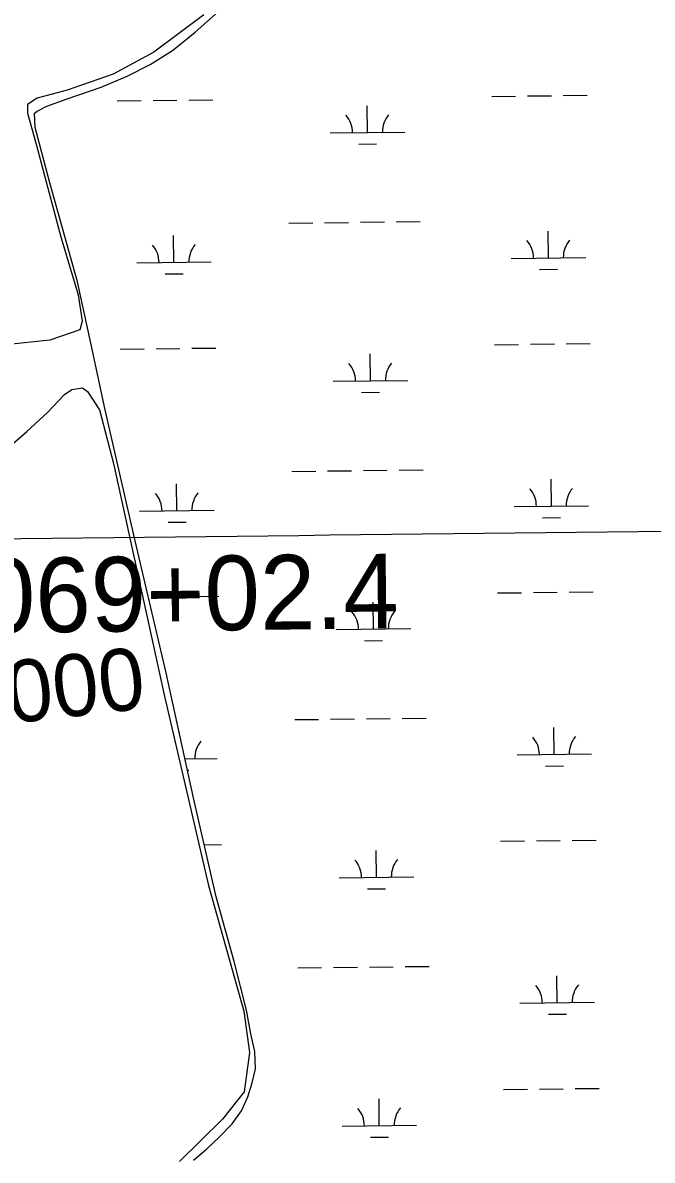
# Model space of a CAD drawing. Extents: x 3694830 to 3732949, y 415201 to 440970.
# Drawn here: x 3718917 to 3719761, y 426079 to 427603 of the extents above; entities that cross this region are included whole.
import ezdxf

# ---------------------------------------------------------------- set-up
doc = ezdxf.new("R2010")
doc.units = 0
for name, color, linetype in [('V-GRID-MAJR', 7, 'Continuous'), ('V-RIVR-EDGE', 7, 'Continuous'), ('V-RIVR-RANG-IDEN', 7, 'Continuous'), ('V-SITE-VEGE', 7, 'Continuous'), ('V-SURV-IDEN', 7, 'Continuous'), ('V-WETL-SWMP', 7, 'Continuous')]:
    doc.layers.add(name, color=color, linetype=linetype)

msp = doc.modelspace()

# ---------------------------------------------------------------- linework, layer by layer
at = {"layer": 'V-GRID-MAJR'}
msp.add_spline([(3698983.973, 426676.689), (3704276.781, 426737.893), (3709569.5810000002, 426799.866), (3714862.3710000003, 426862.61), (3720155.153, 426926.124), (3725447.9250000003, 426990.407), (3730740.688, 427055.46), (3730740.6890000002, 427055.46)], degree=3, dxfattribs=at)
at = {"layer": 'V-RIVR-EDGE'}
msp.add_spline([(3716285.150342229, 433216.70755455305), (3716310.376054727, 433178.2116670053), (3716330.200490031, 433149.67663238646), (3716351.384748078, 433122.4947121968), (3716380.6619774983, 433076.75426305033), (3716399.1355344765, 433050.48336356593), (3716447.785043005, 432976.2089978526), (3716475.253647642, 432930.4730209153), (3716501.833592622, 432891.0694668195), (3716527.508107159, 432851.21599263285), (3716586.0368507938, 432749.33550184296), (3716608.0997060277, 432711.75175305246), (3716608.0896435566, 432707.6823472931), (3716608.0717547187, 432700.4478481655), (3716613.02199377, 432690.94026948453), (3716627.4250269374, 432664.22727627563), (3716633.271752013, 432651.55236812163), (3716643.1890009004, 432639.3195536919), (3716675.1691050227, 432589.50299047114), (3716706.241542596, 432538.3321947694), (3716726.9412209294, 432498.0388629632), (3716741.3252472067, 432463.63921443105), (3716748.5083159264, 432442.8221406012), (3716788.5914538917, 432378.5164541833), (3716817.4332979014, 432339.5594660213), (3716842.1979097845, 432297.4474469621), (3716889.457408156, 432209.6117495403), (3716920.495186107, 432144.4241117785), (3716938.0431876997, 432109.5644806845), (3716956.496619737, 432075.15476968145), (3716988.92217174, 432022.6241512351), (3717009.1808744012, 431986.85349943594), (3717026.296844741, 431960.1337979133), (3717062.315049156, 431897.646798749), (3717093.371833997, 431840.1458163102), (3717112.2628875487, 431799.8569567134), (3717149.120557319, 431711.14266210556), (3717176.537731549, 431644.6075001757), (3717201.24867692, 431580.7919837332), (3717210.6835821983, 431556.3520700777), (3717248.473515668, 431478.93944425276), (3717267.8088990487, 431435.48437323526), (3717289.4072995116, 431392.9280243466), (3717306.4751936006, 431346.7656064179), (3717328.065767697, 431301.04416416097), (3717339.309297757, 431276.599778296), (3717352.341327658, 431244.01210870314), (3717362.697316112, 431226.35230187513), (3717376.210571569, 431205.5195753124), (3717389.256018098, 431178.3577800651), (3717401.373673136, 431141.70294081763), (3717407.1812663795, 431113.2025658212), (3717409.866252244, 431101.89195262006), (3717419.7488415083, 431075.6422961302), (3717452.4923834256, 430968.8518161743), (3717469.0935866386, 430916.8124857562), (3717483.4351269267, 430865.2309017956), (3717505.4543781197, 430810.0130613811), (3717526.565962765, 430753.4409884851), (3717540.488888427, 430715.4252084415), (3717579.0724471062, 430593.2468831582), (3717599.254004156, 430526.27745387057), (3717616.308481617, 430474.68916159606), (3717628.8760567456, 430437.12889190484), (3717638.7441113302, 430405.00120487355), (3717647.6866105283, 430364.284786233), (3717653.484141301, 430331.7150054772), (3717658.415373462, 430314.52077147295), (3717667.8502787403, 430290.08085781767), (3717679.533666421, 430260.6616357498), (3717690.3395749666, 430242.0963984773), (3717695.714018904, 430221.2837968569), (3717698.374407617, 430200.02574735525), (3717697.8529321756, 430171.9931812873), (3717701.423223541, 430152.9936766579), (3717705.9145980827, 430140.7742788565), (3717716.262760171, 430119.94937866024), (3717727.970745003, 430100.4775928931), (3717735.598143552, 430076.49430764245), (3717737.8164385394, 430059.3067819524), (3717749.0476700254, 430029.8886779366), (3717760.7590090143, 430011.77336075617), (3717771.5570911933, 429990.0430301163), (3717776.477142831, 429968.32723415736), (3717783.193520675, 429941.63324783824), (3717791.7252316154, 429917.6477264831), (3717803.4343344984, 429898.62809691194), (3717812.4226738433, 429876.4500822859), (3717819.158058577, 429857.44275129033), (3717834.8829007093, 429816.70956186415), (3717846.5238024, 429770.10840436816), (3717854.1232496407, 429734.8212142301), (3717863.5480924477, 429706.31189481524), (3717878.825250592, 429667.3884482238), (3717891.374936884, 429622.593679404), (3717903.4937099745, 429586.3909963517), (3717917.8240697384, 429530.28785043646), (3717931.7078635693, 429476.44660355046), (3717959.4631526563, 429363.79039162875), (3717976.505331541, 429307.2283812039), (3717987.2463930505, 429262.43808459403), (3718014.107432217, 429153.85351453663), (3718027.5144727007, 429090.0659494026), (3718040.473829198, 429028.0881271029), (3718052.5199288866, 428962.49529134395), (3718057.840706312, 428919.97919233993), (3718056.8950259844, 428903.2516492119), (3718056.857012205, 428887.87833856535), (3718057.7132483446, 428868.43338605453), (3718061.286893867, 428850.7903500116), (3718065.765969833, 428833.5972340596), (3718082.361582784, 428779.2971226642), (3718091.327561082, 428748.075984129), (3718100.2790047, 428710.97681505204), (3718111.4498613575, 428657.14227648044), (3718116.3609685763, 428631.80923095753), (3718128.3075616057, 428525.97449379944), (3718136.7677171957, 428473.0509759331), (3718141.6598175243, 428440.0312750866), (3718152.315907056, 428360.8771076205), (3718163.899788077, 428291.2159841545), (3718171.048197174, 428256.3820682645), (3718178.233501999, 428236.4693068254), (3718193.9158581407, 428178.55418197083), (3718199.7413402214, 428157.2883061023), (3718197.914826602, 428150.05827918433), (3718196.516990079, 428133.3318541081), (3718197.391115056, 428121.12140072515), (3718204.1164373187, 428098.04466397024), (3718215.364439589, 428075.4089028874), (3718227.961084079, 428049.60469427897), (3718240.07538496, 428011.5933864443), (3718242.706704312, 427978.57927585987), (3718251.1064850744, 427901.2393234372), (3718254.151946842, 427852.85078415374), (3718257.693168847, 427822.09521844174), (3718271.4975809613, 427736.1508816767), (3718281.7384100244, 427671.91898671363), (3718287.906479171, 427606.3406856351), (3718295.910006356, 427551.6096610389), (3718303.86545729, 427477.4359200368), (3718310.120734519, 427447.1258022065), (3718323.1359936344, 427407.755789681), (3718345.149654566, 427350.27716828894), (3718351.4094040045, 427321.7756752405), (3718363.483455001, 427267.48674436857), (3718378.280505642, 427217.2605109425), (3718397.9875454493, 427141.24907579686), (3718402.8729374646, 427105.51643777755), (3718405.9172811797, 427056.67574229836), (3718404.85644146, 426993.37611103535), (3718419.5841728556, 426915.1161934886), (3718427.128835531, 426857.673349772), (3718428.7697524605, 426789.8454482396), (3718439.5309389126, 426753.19396314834), (3718453.8926041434, 426709.7511907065), (3718458.333666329, 426677.1847641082), (3718461.822339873, 426625.1778572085), (3718465.3367286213, 426583.5705428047), (3718482.7136682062, 426479.5310138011), (3718492.5235840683, 426423.89120460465), (3718501.0016284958, 426378.20218586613), (3718502.740934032, 426350.1640295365), (3718512.9079716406, 426256.0898256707), (3718518.2276310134, 426213.12157047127), (3718524.0307520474, 426182.8125706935), (3718533.4421782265, 426148.87737693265), (3718540.932056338, 426069.2788796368), (3718548.926639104, 426010.93060547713), (3718557.8054093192, 425944.44128369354), (3718573.419564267, 425858.9446309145), (3718584.546816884, 425787.47600071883), (3718587.6079313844, 425745.4176481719), (3718587.5598551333, 425725.9749317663), (3718607.5144475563, 425567.2177947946), (3718614.553287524, 425488.07257174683), (3718638.2224000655, 425368.6440793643), (3718641.2633896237, 425318.44691529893), (3718641.093445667, 425249.71917358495), (3718640.1008071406, 425214.0010702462), (3718649.842521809, 425130.7797331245), (3718658.7335906, 425069.2641294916), (3718661.819302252, 425037.15321324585), (3718660.4114032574, 425016.35738241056), (3718674.9568921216, 424864.3960049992), (3718675.7337465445, 424812.8479626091), (3718692.623870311, 424694.7927095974), (3718696.053287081, 424618.8215243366), (3718696.3992283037, 424575.8655677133), (3718706.120818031, 424484.50541907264), (3718711.8680364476, 424431.58860952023), (3718715.414848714, 424403.0938247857), (3718735.932284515, 424289.09903311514), (3718746.6017906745, 424215.3707399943), (3718759.902616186, 424108.62833628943), (3718772.361740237, 424027.20891563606), (3718777.7160592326, 423998.2575024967), (3718795.9078670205, 423858.0432417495), (3718805.722255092, 423804.2120573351), (3718812.4363968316, 423776.6137586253), (3718828.995114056, 423707.3924927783), (3718835.666769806, 423662.61225864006), (3718835.0893917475, 423611.97188279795), (3718835.0021836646, 423576.70369954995), (3718839.347093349, 423505.2518401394), (3718842.400381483, 423460.0283942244), (3718850.4217975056, 423412.53186875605), (3718863.399042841, 423357.7885455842), (3718870.556396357, 423326.57187925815), (3718873.558254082, 423260.5492483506), (3718878.8566704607, 423208.99002543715), (3718893.6280058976, 423148.3641995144), (3718898.9990956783, 423126.1951293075), (3718912.449740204, 423080.0416557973), (3718927.228902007, 423022.5809232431), (3718930.7723601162, 422992.72966992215), (3718937.449606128, 422950.2102167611), (3718945.9175880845, 422900.45179226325), (3718952.6261395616, 422870.5927125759), (3718968.7192839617, 422795.94669043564), (3718969.558749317, 422769.7193949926), (3718968.1251351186, 422738.52397166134), (3718972.1185133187, 422707.7672878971), (3718981.0464778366, 422661.1728387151), (3718990.8496853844, 422602.8200923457), (3719006.889163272, 422506.4705728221), (3719010.8098680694, 422446.3237363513), (3719014.374569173, 422425.06345074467), (3719022.4351170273, 422393.39239211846), (3719033.201893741, 422359.001688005), (3719050.257489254, 422307.86555192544), (3719062.772515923, 422249.0539410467), (3719077.096167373, 422190.2378579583), (3719087.846173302, 422149.0648109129)], degree=3, dxfattribs=at)
at = {"layer": 'V-SITE-VEGE'}
for points in [[(3719159.383, 427613.662), (3719092.375, 427563.70900000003), (3719038.134, 427533.954), (3718976.452, 427512.71), (3718936.043, 427502.08900000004), (3718923.2800000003, 427493.588), (3718923.276, 427481.89), (3718934.957, 427440.416), (3718949.824, 427382.988), (3718967.877, 427315.993), (3718991.2430000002, 427238.358), (3718996.5470000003, 427203.267), (3718993.3540000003, 427191.569), (3718952.941, 427177.762), (3718833.842, 427165.04600000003)], [(3718890.696, 427027.645), (3718922.336, 427055.31200000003), (3718950.0160000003, 427080.603), (3718972.954, 427105.107), (3718982.447, 427111.429), (3718996.6780000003, 427113.79600000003), (3719003.793, 427109.049), (3719019.599, 427084.533), (3719038.549, 427012.572), (3719106.441, 426702.599), (3719165.6520000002, 426447.185), (3719213.035, 426278.751), (3719220.9220000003, 426223.402), (3719213.789, 426170.42600000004), (3719184.519, 426134.066), (3719126.779, 426077.156)]]:
    msp.add_lwpolyline(points, dxfattribs=at)
at = {"layer": 'V-WETL-SWMP'}
for p, q in [((3719148.019884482, 427590.3229816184), (3719179.261923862, 427617.98598788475)), ((3719117.5698445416, 427565.8219752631), (3719148.019884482, 427590.3229816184)), ((3719087.516849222, 427547.25197600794), (3719117.5698445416, 427565.8219752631)), ((3719056.674898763, 427531.447983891), (3719087.516849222, 427547.2519760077)), ((3719021.878904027, 427516.83298472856), (3719056.674898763, 427531.447983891)), ((3718976.408910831, 427501.0349858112), (3719021.878904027, 427516.83298472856)), ((3718949.1268701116, 427491.16097933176), (3718976.408910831, 427501.0349858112)), ((3719043.511134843, 427498.3257887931), (3719075.508856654, 427498.7074341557)), ((3719091.5077175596, 427498.89825683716), (3719123.5054393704, 427499.2799021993)), ((3719139.504300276, 427499.4707248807), (3719171.502022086, 427499.85237024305)), ((3719545.3834023, 427504.3117531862), (3719577.3811241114, 427504.6933985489)), ((3719593.3799850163, 427504.8842212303), (3719625.377706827, 427505.2658665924)), ((3719641.376567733, 427505.4566892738), (3719673.3742895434, 427505.83833463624)), ((3718932.5190959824, 427481.6780152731), (3718936.077961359, 427484.4449938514)), ((3718933.303051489, 427462.702008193), (3718932.5190959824, 427481.6780152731)), ((3718936.077961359, 427484.4449938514), (3718949.1268701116, 427491.16097933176)), ((3719378.8850407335, 427455.8925804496), (3719378.455688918, 427491.8900199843)), ((3718953.04378263, 427388.36996541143), (3718933.303051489, 427462.702008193)), ((3719328.888600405, 427455.29625957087), (3719428.881481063, 427456.4889013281)), ((3719367.0699319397, 427440.3195609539), (3719391.068223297, 427440.60579497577)), ((3718990.160182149, 427255.91602898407), (3718953.04378263, 427388.36996541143)), ((3719273.4806668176, 427334.55585422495), (3719305.478388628, 427334.93749958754)), ((3719321.477249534, 427335.1283222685), (3719353.4749713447, 427335.50996763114)), ((3719369.4738322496, 427335.7007903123), (3719401.471554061, 427336.0824356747)), ((3719417.4704149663, 427336.2732583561), (3719449.468136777, 427336.6549037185)), ((3719119.5048441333, 427281.9737344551), (3719119.075492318, 427317.9711739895)), ((3719621.3771115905, 427287.95969884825), (3719620.947759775, 427323.95713838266)), ((3719069.5084038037, 427281.3774135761), (3719169.501284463, 427282.57005533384)), ((3719571.380671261, 427287.36337796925), (3719671.37355192, 427288.556019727)), ((3719107.689735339, 427266.40071495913), (3719131.6880266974, 427266.6869489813)), ((3719609.562002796, 427272.3866793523), (3719633.560294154, 427272.67291337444)), ((3719009.1061369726, 427169.7240217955), (3718990.160182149, 427255.91602898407)), ((3719027.261913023, 427084.3229861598), (3719009.1061369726, 427169.7240217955)), ((3719047.478763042, 427165.6744499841), (3719079.476484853, 427166.0560953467)), ((3719095.4753457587, 427166.2469180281), (3719127.473067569, 427166.6285633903)), ((3719143.4719284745, 427166.8193860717), (3719175.4696502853, 427167.20103143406)), ((3719382.8526689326, 427123.2412416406), (3719382.4233171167, 427159.2386811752)), ((3719549.351030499, 427171.6604143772), (3719581.34875231, 427172.0420597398)), ((3719597.3476132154, 427172.2328824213), (3719629.345335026, 427172.6145277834)), ((3719645.3441959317, 427172.8053504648), (3719677.3419177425, 427173.1869958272)), ((3719332.8562286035, 427122.6449207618), (3719432.8491092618, 427123.83756251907)), ((3719371.037560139, 427107.6682221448), (3719395.0358514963, 427107.9544561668)), ((3719067.5262238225, 426908.7750356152), (3719027.261913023, 427084.3229861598)), ((3719277.4482950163, 427001.9045154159), (3719309.446016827, 427002.28616077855)), ((3719325.4448777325, 427002.4769834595), (3719357.442599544, 427002.8586288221)), ((3719373.441460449, 427003.04945150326), (3719405.4391822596, 427003.4310968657)), ((3719421.4380431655, 427003.6219195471), (3719453.435764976, 427004.00356490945)), ((3719625.344739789, 426955.30836003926), (3719624.9153879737, 426991.30579957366)), ((3719123.472472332, 426949.32239564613), (3719123.043120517, 426985.31983518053)), ((3719073.4760320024, 426948.7260747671), (3719173.4689126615, 426949.91871652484)), ((3719575.3482994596, 426954.71203916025), (3719675.3411801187, 426955.90468091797)), ((3719111.6573635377, 426933.74937615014), (3719135.655654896, 426934.03561017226)), ((3719613.529630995, 426939.73534054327), (3719637.527922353, 426940.02157456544)), ((3719108.9749538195, 426732.0409926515), (3719067.5262238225, 426908.7750356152)), ((3719553.3186586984, 426839.00907556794), (3719585.3163805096, 426839.3907209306)), ((3719601.315241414, 426839.581543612), (3719633.3129632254, 426839.9631889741)), ((3719649.311824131, 426840.1540116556), (3719681.3095459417, 426840.53565701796)), ((3719099.442973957, 426833.5955792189), (3719131.440695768, 426833.977224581)), ((3719147.4395566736, 426834.1680472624), (3719179.4372784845, 426834.54969262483)), ((3719386.820297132, 426790.5899028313), (3719386.3909453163, 426826.587342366)), ((3719336.8238568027, 426789.9935819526), (3719436.8167374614, 426791.18622370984)), ((3719375.0051883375, 426775.0168833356), (3719399.0034796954, 426775.3031173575)), ((3719145.683907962, 426564.4009853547), (3719108.9749538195, 426732.0409926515)), ((3719425.4056713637, 426670.97058073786), (3719457.403393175, 426671.3522261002)), ((3719281.4159232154, 426669.25317660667), (3719313.4136450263, 426669.63482196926)), ((3719329.412505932, 426669.8256446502), (3719361.410227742, 426670.20729001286)), ((3719377.409088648, 426670.39811269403), (3719409.4068104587, 426670.7797580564)), ((3719629.3123679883, 426622.65702122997), (3719628.8830161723, 426658.65446076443)), ((3719127.0484930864, 426649.5039570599), (3719127.0107487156, 426652.6684963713)), ((3719134.2203656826, 426616.75192686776), (3719177.4365408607, 426617.2673777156)), ((3719579.3159276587, 426622.060700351), (3719679.308808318, 426623.25334210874)), ((3719137.5908049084, 426601.3600294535), (3719139.623283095, 426601.38427136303)), ((3719617.4972591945, 426607.08400173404), (3719641.495550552, 426607.37023575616)), ((3719176.0790403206, 426431.95000641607), (3719145.683907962, 426564.4009853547)), ((3719557.2862868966, 426506.35773675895), (3719589.284008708, 426506.7393821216)), ((3719605.2828696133, 426506.930204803), (3719637.280591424, 426507.31185016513)), ((3719653.2794523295, 426507.50267284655), (3719685.27717414, 426507.88431820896)), ((3719160.0909572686, 426501.62028212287), (3719183.404906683, 426501.8983538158)), ((3719390.7879253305, 426457.9385640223), (3719390.358573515, 426493.936003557)), ((3719340.791485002, 426457.3422431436), (3719440.7843656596, 426458.53488490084)), ((3719378.9728165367, 426442.3655445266), (3719402.971107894, 426442.6517785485)), ((3719200.1649051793, 426345.3599849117), (3719176.0790403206, 426431.95000641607)), ((3719216.7458146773, 426280.122970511), (3719200.1649051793, 426345.3599849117)), ((3719285.3835514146, 426336.6018377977), (3719317.381273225, 426336.98348316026)), ((3719333.3801341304, 426337.1743058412), (3719365.377855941, 426337.55595120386)), ((3719381.3767168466, 426337.74677388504), (3719413.374438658, 426338.1284192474)), ((3719429.373299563, 426338.3192419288), (3719461.3710213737, 426338.7008872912)), ((3719633.2799961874, 426290.005682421), (3719632.8506443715, 426326.0031219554)), ((3719583.283555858, 426289.40936154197), (3719683.276436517, 426290.60200329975)), ((3719222.6648145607, 426248.0979704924), (3719216.7458146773, 426280.122970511)), ((3719621.464887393, 426274.43266292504), (3719645.463178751, 426274.71889694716)), ((3719227.795725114, 426224.76995625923), (3719222.664814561, 426248.0979704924)), ((3719228.578681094, 426201.44494925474), (3719227.7957251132, 426224.76995625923)), ((3719224.223637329, 426182.4699422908), (3719228.578681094, 426201.44494925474)), ((3719218.2865937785, 426163.88993536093), (3719224.223637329, 426182.4699422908)), ((3719561.253915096, 426173.7063979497), (3719593.251636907, 426174.0880433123)), ((3719609.2504978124, 426174.2788659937), (3719641.248219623, 426174.6605113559)), ((3719657.247080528, 426174.8513340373), (3719689.2448023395, 426175.2329793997)), ((3719209.9776849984, 426145.3119498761), (3719218.2865937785, 426163.88993536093)), ((3719394.7555535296, 426125.2872252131), (3719394.326201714, 426161.2846647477)), ((3719197.7155975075, 426127.9209359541), (3719209.9776849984, 426145.3119498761)), ((3719180.3145559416, 426110.13692934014), (3719197.7155975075, 426127.9209359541)), ((3719344.7591132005, 426124.6909043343), (3719444.7519938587, 426125.88354609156)), ((3719162.9135139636, 426093.93392266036), (3719180.3145559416, 426110.13692934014)), ((3719382.940444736, 426109.7142057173), (3719406.9387360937, 426110.00043973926)), ((3719145.51251677, 426078.9169231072), (3719162.9135139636, 426093.93392266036))]:
    msp.add_line(p, q, dxfattribs=at)
for centre, radius, start, end in [((3719323.6403748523, 427455.70849953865), 35.24628790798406, 359.91152952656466, 41.455187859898), ((3719434.1183811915, 427457.026200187), 35.246287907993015, 139.91152663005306, 181.4551849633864), ((3719566.1324457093, 427287.7756179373), 35.24628790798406, 359.91152952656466, 41.455187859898), ((3719676.6104520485, 427289.0933185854), 35.246287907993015, 139.91152663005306, 181.4551849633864), ((3719064.260178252, 427281.7896535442), 35.24628790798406, 359.91152952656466, 41.455187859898), ((3719174.7381845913, 427283.10735419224), 35.246287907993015, 139.91152663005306, 181.4551849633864), ((3719327.6080030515, 427123.05716072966), 35.24628790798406, 359.91152952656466, 41.455187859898), ((3719438.08600939, 427124.374861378), 35.246287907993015, 139.91152663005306, 181.4551849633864), ((3719570.1000739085, 426955.12427912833), 35.24628790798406, 359.91152952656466, 41.455187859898), ((3719680.578080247, 426956.44197977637), 35.246287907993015, 139.91152663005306, 181.4551849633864), ((3719068.2278064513, 426949.1383147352), 35.24628790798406, 359.91152952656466, 41.455187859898), ((3719178.70581279, 426950.45601538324), 35.246287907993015, 139.91152663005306, 181.4551849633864), ((3719331.5756312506, 426790.40582192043), 35.24628790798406, 359.91152952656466, 41.455187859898), ((3719442.0536375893, 426791.7235225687), 35.246287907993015, 139.91152663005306, 181.4551849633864), ((3719182.673440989, 426617.804676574), 35.246287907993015, 139.91152663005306, 181.4551849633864), ((3719574.0677021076, 426622.47294031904), 35.24628790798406, 359.91152952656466, 41.455187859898), ((3719684.5457084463, 426623.79064096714), 35.246287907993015, 139.91152663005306, 181.4551849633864), ((3719335.5432594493, 426457.7544831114), 35.24628790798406, 359.91152952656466, 41.455187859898), ((3719446.021265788, 426459.0721837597), 35.246287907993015, 139.91152663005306, 181.4551849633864), ((3719578.0353303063, 426289.82160151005), 35.24628790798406, 359.91152952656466, 41.455187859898), ((3719688.513336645, 426291.13930215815), 35.246287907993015, 139.91152663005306, 181.4551849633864), ((3719339.5108876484, 426125.10314430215), 35.24628790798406, 359.91152952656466, 41.455187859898), ((3719449.988893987, 426126.4208449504), 35.246287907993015, 139.91152663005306, 181.4551849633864)]:
    msp.add_arc(centre, radius, start, end, dxfattribs=at)

# ---------------------------------------------------------------- texts
at = {"layer": 'V-RIVR-RANG-IDEN'}
msp.add_text('U-000', height=83.00000000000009, rotation=6.46432571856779, dxfattribs=at).set_placement((3718783.5450151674, 426650.735623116))
at = {"layer": 'V-SURV-IDEN'}
msp.add_text('1069+02.4', height=100.00000000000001, rotation=0.6644880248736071, dxfattribs=at).set_placement((3718785.3398085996, 426784.36520229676))

doc.saveas('drawing.dxf')
